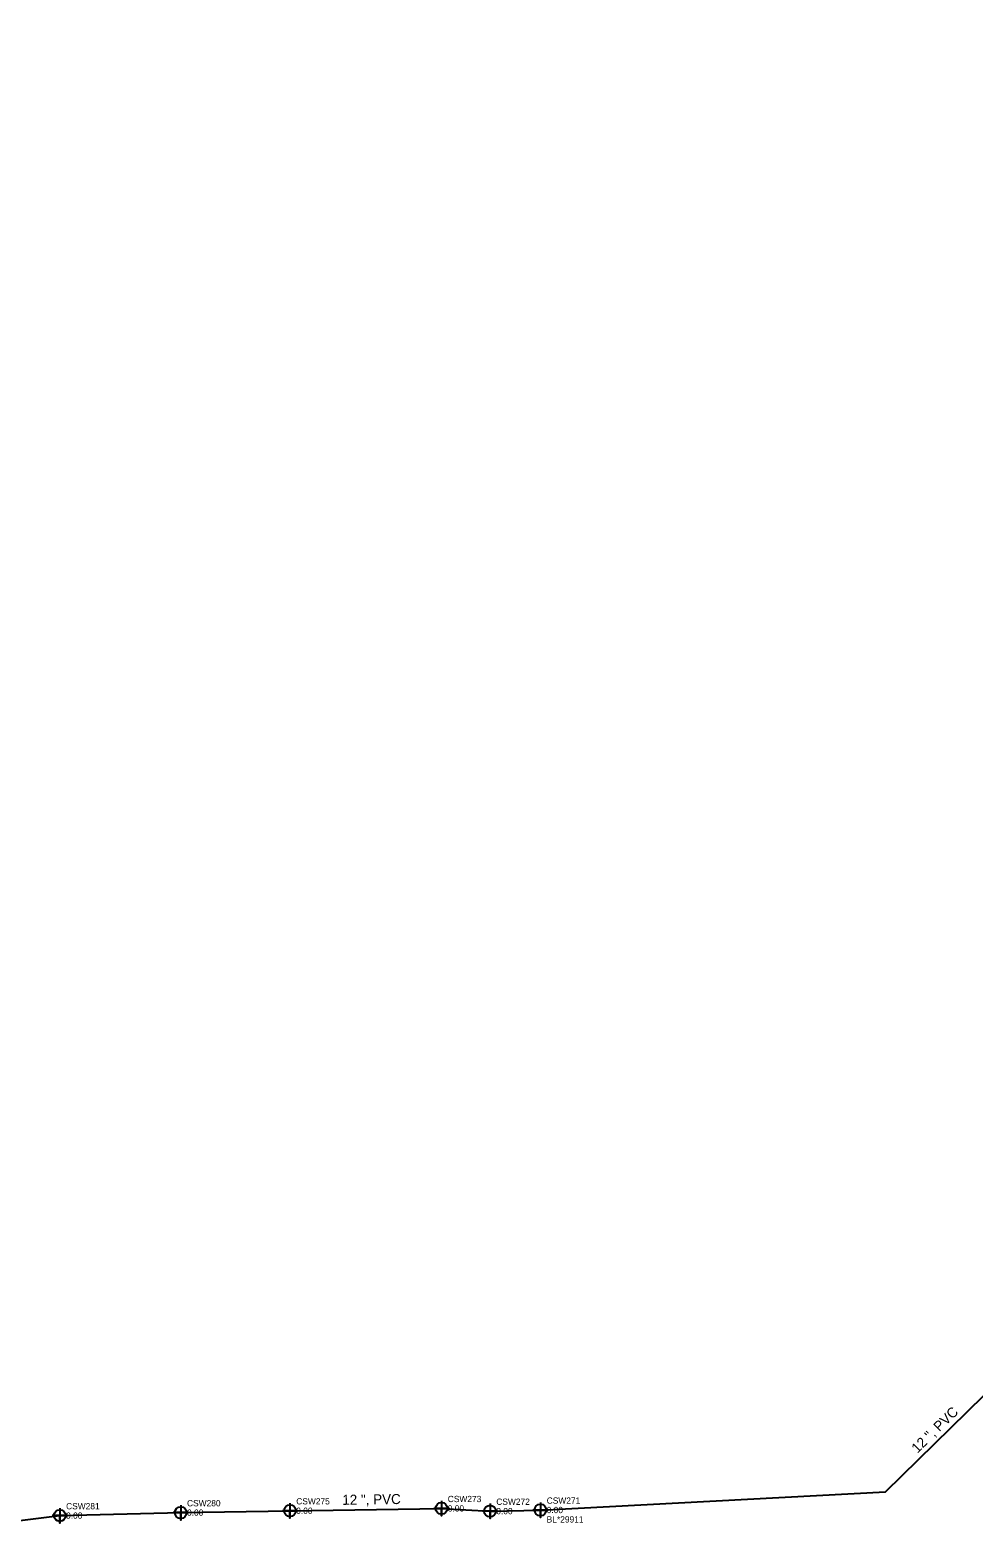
# Model space of a CAD drawing. Extents: x 1182504 to 1186036, y 573002 to 575111.
# Drawn here: x 1184495 to 1184871, y 574445 to 575047 of the extents above; entities that cross this region are included whole.
import ezdxf

# ---------------------------------------------------------------- set-up
doc = ezdxf.new("R2010")
doc.units = 0
for name, color, linetype in [('Exist Utilities Water UG Line SUE LOS B', 7, 'Continuous'), ('Exist Utilities Water UG Line SUE LOS B Cogo Comment', 7, 'Continuous'), ('Exist Utilities Water UG Line SUE LOS B Cogo Elevation', 7, 'Continuous'), ('Exist Utilities Water UG Line SUE LOS B Cogo Number', 7, 'Continuous'), ('Exist Utilities Water UG Line SUE LOS B Cogo Point CELL', 7, 'Continuous'), ('Exist Utilities Water UG Line SUE LOS B Text', 7, 'Continuous'), ('Exist Utilities Water UG Line SUE LOS C', 7, 'Continuous'), ('Exist Utilities Water UG Line SUE LOS C Text', 7, 'Continuous')]:
    doc.layers.add(name, color=color, linetype=linetype)

msp = doc.modelspace()

# ---------------------------------------------------------------- linework, layer by layer
at = {"layer": 'Exist Utilities Water UG Line SUE LOS B'}
msp.add_lwpolyline([(1184300.95, 574453.14), (1184304.21, 574453.9), (1184323.5, 574455.17), (1184363.75, 574458.3), (1184391.73, 574445.48), (1184462.04, 574448.86), (1184506.81, 574454.35), (1184555.01, 574455.54), (1184598.54, 574456.3), (1184658.94, 574457.22), (1184678.28, 574456.14), (1184698.37, 574456.58)], dxfattribs=at)
at = {"layer": 'Exist Utilities Water UG Line SUE LOS B Cogo Point CELL'}
for points in [[(1184506.81, 574457.35), (1184506.81, 574451.35), (1184506.81, 574454.35), (1184509.81, 574454.35), (1184503.81, 574454.35)], [(1184555.01, 574458.54), (1184555.01, 574452.54), (1184555.01, 574455.54), (1184558.01, 574455.54), (1184552.01, 574455.54)], [(1184598.54, 574459.3), (1184598.54, 574453.3), (1184598.54, 574456.3), (1184601.54, 574456.3), (1184595.54, 574456.3)], [(1184658.94, 574460.22), (1184658.94, 574454.22), (1184658.94, 574457.22), (1184661.94, 574457.22), (1184655.94, 574457.22)], [(1184678.28, 574459.14), (1184678.28, 574453.14), (1184678.28, 574456.14), (1184681.28, 574456.14), (1184675.28, 574456.14)], [(1184698.37, 574459.58), (1184698.37, 574453.58), (1184698.37, 574456.58), (1184701.37, 574456.58), (1184695.37, 574456.58)]]:
    msp.add_lwpolyline(points, dxfattribs=at)
for centre in [(1184506.81, 574454.35), (1184555.01, 574455.54), (1184598.54, 574456.3), (1184658.94, 574457.22), (1184678.28, 574456.14), (1184698.37, 574456.58)]:
    msp.add_circle(centre, 2.34, dxfattribs=at)
at = {"layer": 'Exist Utilities Water UG Line SUE LOS C'}
msp.add_lwpolyline([(1184698.37, 574456.58), (1184835.97, 574463.78), (1185103.91, 574726.55), (1185431.28, 575046.78)], dxfattribs=at)

# ---------------------------------------------------------------- texts
at = {"layer": 'Exist Utilities Water UG Line SUE LOS B Cogo Comment'}
msp.add_text('BL*29911', height=2.5, dxfattribs=at).set_placement((1184700.87, 574451.58))
at = {"layer": 'Exist Utilities Water UG Line SUE LOS B Cogo Elevation'}
for p in [(1184509.31, 574453.1), (1184557.51, 574454.29), (1184601.04, 574455.05), (1184661.44, 574455.97), (1184680.78, 574454.89), (1184700.87, 574455.33)]:
    msp.add_text('0.00', height=2.5, dxfattribs=at).set_placement(p)
at = {"layer": 'Exist Utilities Water UG Line SUE LOS B Cogo Number'}
for s, p in [('CSW273', (1184661.44, 574459.72)), ('CSW271', (1184700.87, 574459.08)), ('CSW281', (1184509.31, 574456.85)), ('CSW280', (1184557.51, 574458.04)), ('CSW275', (1184601.04, 574458.8)), ('CSW272', (1184680.78, 574458.64))]:
    msp.add_text(s, height=2.5, dxfattribs=at).set_placement(p)
at = {"layer": 'Exist Utilities Water UG Line SUE LOS B Text'}
msp.add_text('12 ", PVC', height=4, rotation=0.87213, dxfattribs=at).set_placement((1184619.43, 574458.62))
at = {"layer": 'Exist Utilities Water UG Line SUE LOS C Text'}
msp.add_text('12 ", PVC', height=4, rotation=44.44123, dxfattribs=at).set_placement((1184848.62, 574478.99))

doc.saveas('drawing.dxf')
